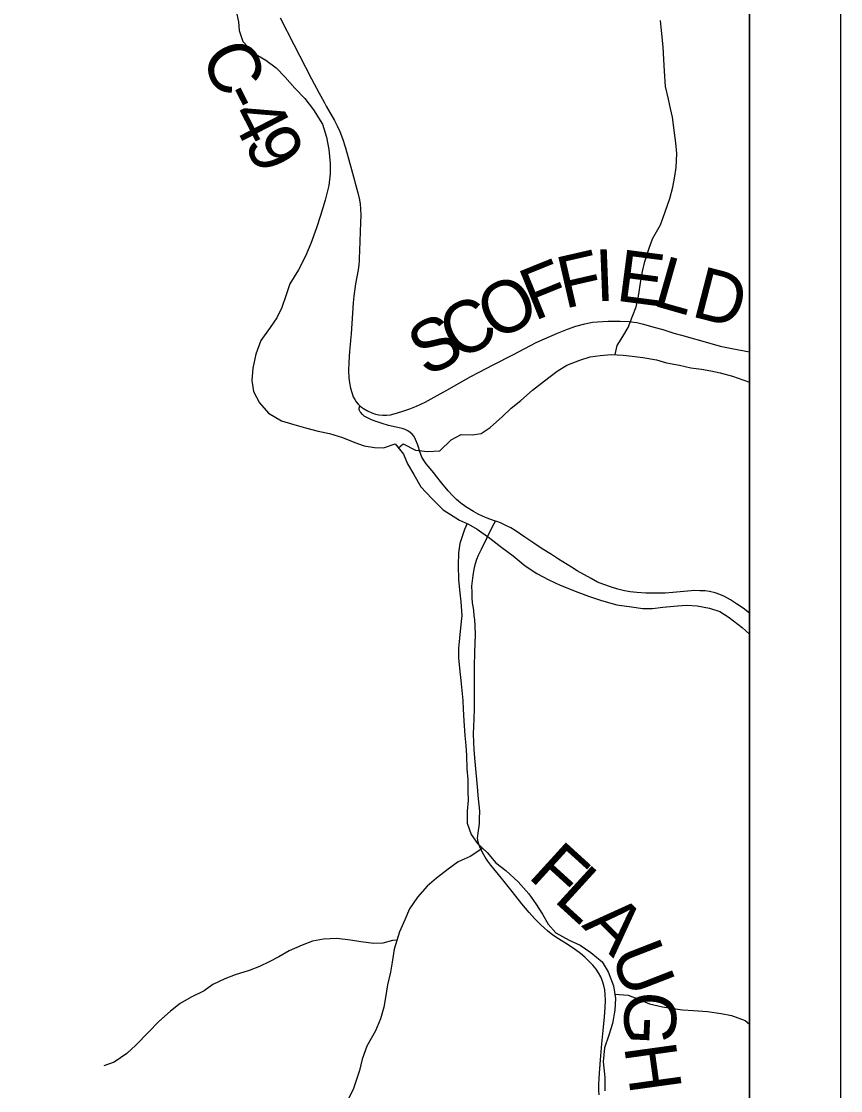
# Model space of a CAD drawing. Extents: x 0 to 34, y 0 to 22.
# Drawn here: x 8.316 to 9.214, y 14.754 to 15.927 of the extents above; entities that cross this region are included whole.
import ezdxf

# ---------------------------------------------------------------- set-up
doc = ezdxf.new("R2010")
doc.units = 0
for name, color, linetype in [('Default', 7, 'Continuous'), ('GM_X_County_Road', 7, 'Continuous'), ('GM_X_County_Road_Text', 7, 'Continuous'), ('GM_X_Minor_River', 7, 'Continuous'), ('GM_X_Township_Road', 7, 'Continuous'), ('GM_X_Township_Road_Text', 7, 'Continuous'), ('SH_Cut_Line', 7, 'Continuous'), ('SH_Data', 7, 'Continuous')]:
    doc.layers.add(name, color=color, linetype=linetype)

msp = doc.modelspace()

# ---------------------------------------------------------------- linework, layer by layer
at = {"layer": 'Default'}
msp.add_lwpolyline([(9.1142, 14.0996), (9.1142, 17.7402)], dxfattribs=at)
at = {"layer": 'GM_X_County_Road'}
for points in [[(8.5997, 15.9311), (8.6145, 15.9017), (8.634, 15.8643), (8.6424, 15.8483), (8.6477, 15.8385), (8.6502, 15.8342), (8.6592, 15.8186), (8.6623, 15.8125), (8.6652, 15.8062), (8.668, 15.7986), (8.6712, 15.7885), (8.6779, 15.7646), (8.6849, 15.7389), (8.6865, 15.7315), (8.6873, 15.7266), (8.6877, 15.7216), (8.6879, 15.7141), (8.6877, 15.7066), (8.6868, 15.6756), (8.6864, 15.6669), (8.6863, 15.6644), (8.6858, 15.6601), (8.685, 15.6545), (8.6823, 15.6392), (8.6805, 15.6257), (8.6798, 15.6184), (8.6773, 15.5843), (8.6767, 15.5769), (8.6763, 15.5726), (8.6755, 15.5652), (8.6749, 15.5528), (8.6747, 15.5442), (8.6751, 15.5361), (8.6757, 15.5307), (8.6768, 15.5246), (8.6781, 15.5199), (8.6798, 15.5153), (8.6814, 15.5121), (8.683, 15.5096), (8.685, 15.5073), (8.687, 15.5054)], [(8.687, 15.5054), (8.6889, 15.5038), (8.6911, 15.5024), (8.6953, 15.5), (8.7003, 15.4977), (8.7043, 15.4962), (8.7079, 15.4954), (8.7121, 15.495), (8.7163, 15.4951), (8.7205, 15.4956), (8.7247, 15.4965), (8.7329, 15.499), (8.7417, 15.502), (8.7491, 15.5051), (8.7586, 15.5095), (8.7717, 15.5166), (8.7858, 15.5244), (8.8078, 15.5372), (8.8177, 15.5424), (8.8332, 15.5502), (8.8556, 15.5618), (8.8804, 15.5747), (8.8894, 15.579), (8.9036, 15.5852), (8.9146, 15.5895), (8.924, 15.5927), (8.9336, 15.5954), (8.9372, 15.5962), (8.942, 15.5971), (8.9476, 15.5976), (8.9593, 15.5982), (8.9724, 15.5982), (8.9823, 15.5978), (8.9873, 15.5973), (8.9909, 15.5967), (8.9981, 15.5949), (9.0095, 15.5916), (9.0191, 15.589), (9.0315, 15.5851), (9.0399, 15.5828), (9.0709, 15.574), (9.0823, 15.5709), (9.095, 15.5681), (9.1084, 15.5656), (9.1142, 15.5645)], [(8.8356, 15.3789), (8.8285, 15.3814), (8.8216, 15.3841), (8.8166, 15.3865), (8.8117, 15.3892), (8.8033, 15.3945), (8.7978, 15.3986), (8.793, 15.4025), (8.7886, 15.4068), (8.7839, 15.4119), (8.777, 15.4206), (8.77, 15.4293), (8.768, 15.4317), (8.7596, 15.4417), (8.7575, 15.4448), (8.7551, 15.4491), (8.7534, 15.4531), (8.7501, 15.4631), (8.7481, 15.4684), (8.7464, 15.4716), (8.7445, 15.4741), (8.7422, 15.4762), (8.7396, 15.4779), (8.7367, 15.4792), (8.7334, 15.4804), (8.7268, 15.4819), (8.7184, 15.4838), (8.7113, 15.4858), (8.7048, 15.488), (8.6996, 15.4901), (8.6945, 15.4925), (8.6919, 15.4941), (8.69, 15.4957), (8.688, 15.4979), (8.6872, 15.4989), (8.6866, 15.5002), (8.6864, 15.5014), (8.6863, 15.5027), (8.6865, 15.504), (8.687, 15.5054)], [(9.1142, 15.2779), (9.1073, 15.2832), (9.1002, 15.2882), (9.0933, 15.2924), (9.0868, 15.296), (9.0817, 15.2983), (9.0765, 15.3003), (9.0705, 15.3015), (9.0656, 15.3022), (9.06, 15.3025), (9.0544, 15.3026), (9.0464, 15.3021), (9.0303, 15.3005), (9.0217, 15.2999), (9.0118, 15.2996), (9.0007, 15.2999), (8.9907, 15.3005), (8.9834, 15.3014), (8.9772, 15.3025), (8.97, 15.3042), (8.9617, 15.3066), (8.9546, 15.3091), (8.9477, 15.312), (8.9406, 15.3157), (8.9255, 15.3244), (8.9192, 15.3283), (8.905, 15.3372), (8.8971, 15.3421), (8.8871, 15.3484), (8.8778, 15.3546), (8.868, 15.3611), (8.8572, 15.3684), (8.8524, 15.3713), (8.8464, 15.3744), (8.8413, 15.3768), (8.8373, 15.3783), (8.8356, 15.3789)]]:
    msp.add_lwpolyline(points, dxfattribs=at)
at = {"layer": 'GM_X_Minor_River'}
for points in [[(8.5511, 15.9403), (8.5539, 15.9266), (8.5545, 15.9171), (8.5585, 15.9052), (8.5709, 15.8925), (8.584, 15.8847), (8.5953, 15.8762), (8.6046, 15.8662), (8.6158, 15.8539), (8.6266, 15.8427), (8.6363, 15.83), (8.646, 15.8143), (8.6503, 15.8002), (8.6531, 15.7865), (8.6544, 15.7713), (8.6543, 15.7599), (8.6529, 15.747), (8.6489, 15.7311), (8.6437, 15.7141), (8.6394, 15.7005), (8.6331, 15.6835), (8.6275, 15.6695), (8.6197, 15.6544), (8.6104, 15.6393), (8.6061, 15.6272), (8.6013, 15.6133), (8.5958, 15.6019), (8.5885, 15.5914), (8.5784, 15.5771), (8.5729, 15.562), (8.5696, 15.5465), (8.5687, 15.5332), (8.5704, 15.521), (8.577, 15.5088), (8.5867, 15.4972), (8.601, 15.4887), (8.6146, 15.4847), (8.6275, 15.4811), (8.6414, 15.4774), (8.6539, 15.475), (8.6679, 15.4706), (8.6814, 15.4651), (8.6916, 15.4615), (8.703, 15.4595), (8.7128, 15.4593), (8.7258, 15.4637), (8.7347, 15.4522), (8.7391, 15.4418), (8.7462, 15.43), (8.7539, 15.4166), (8.7659, 15.4035), (8.7782, 15.3911), (8.7962, 15.3799), (8.806, 15.3755), (8.8158, 15.3701), (8.8297, 15.36), (8.8428, 15.3499), (8.8552, 15.3406), (8.8683, 15.3298), (8.8811, 15.3213), (8.8942, 15.3143), (8.9067, 15.3084), (8.9259, 15.3009)], [(8.9671, 15.5615), (8.9693, 15.5715), (8.9755, 15.5813), (8.9813, 15.5914), (8.9861, 15.6039), (8.99, 15.6141), (8.9924, 15.6255), (8.9953, 15.6425), (8.997, 15.6528), (8.9994, 15.6637), (9.0038, 15.6773), (9.0081, 15.6887), (9.0167, 15.7038), (9.0214, 15.717), (9.027, 15.7329), (9.0302, 15.7453), (9.0322, 15.7552), (9.0339, 15.7669), (9.0345, 15.7821), (9.0336, 15.7939), (9.0322, 15.805), (9.0298, 15.8221), (9.0277, 15.8316), (9.0255, 15.8419), (9.0223, 15.8556), (9.021, 15.8724), (9.0205, 15.8853), (9.0195, 15.8993), (9.0179, 15.9172), (9.0166, 15.9283)], [(8.7293, 15.4592), (8.7345, 15.4636), (8.7481, 15.4565), (8.7613, 15.4552), (8.7746, 15.4561), (8.7873, 15.4681), (8.798, 15.4737), (8.8101, 15.4735), (8.82, 15.4749), (8.8299, 15.4816), (8.8434, 15.4935), (8.853, 15.5029), (8.8634, 15.5111), (8.8764, 15.5227), (8.8895, 15.5327), (8.9033, 15.5432), (8.914, 15.5499), (8.9281, 15.5554), (8.9395, 15.559), (8.9505, 15.5604), (8.9627, 15.5617), (8.9756, 15.5611), (8.9858, 15.5598), (8.9975, 15.5582), (9.0123, 15.5557), (9.0232, 15.5525), (9.0376, 15.55), (9.0501, 15.5471), (9.0618, 15.5455), (9.072, 15.5438), (9.0822, 15.5417), (9.0958, 15.5377), (9.1142, 15.5313)], [(8.8047, 15.3761), (8.8018, 15.3695), (8.7966, 15.3544), (8.7953, 15.3442), (8.7947, 15.3301), (8.7953, 15.3149), (8.7963, 15.3035), (8.7976, 15.2902), (8.7989, 15.2754), (8.7975, 15.2617), (8.7962, 15.2503), (8.7953, 15.2393), (8.7952, 15.2287), (8.7965, 15.2139), (8.7978, 15.204), (8.7988, 15.1929), (8.7998, 15.1819), (8.8004, 15.1724), (8.801, 15.1595), (8.8023, 15.1435), (8.8032, 15.1325), (8.8038, 15.1218), (8.8044, 15.107), (8.8054, 15.0952), (8.8055, 15.0827), (8.8058, 15.0724), (8.8048, 15.0607), (8.8047, 15.0474), (8.809, 15.0348), (8.8161, 15.0252), (8.8266, 15.0151), (8.8363, 15.004), (8.8471, 14.9955), (8.8606, 14.9831), (8.8722, 14.9697), (8.88, 14.9589), (8.8874, 14.9474), (8.8937, 14.9367), (8.9019, 14.9271), (8.9165, 14.9189), (8.9286, 14.9134), (8.9402, 14.9056), (8.9526, 14.8952), (8.9592, 14.8841), (8.9651, 14.8688), (8.9672, 14.8551), (8.9666, 14.8422), (8.9641, 14.8274), (8.9601, 14.8149), (8.9554, 14.801), (8.954, 14.7854), (8.9557, 14.7683), (8.9558, 14.7535)], [(8.9259, 15.3009), (8.9376, 15.2965), (8.9519, 15.2918), (8.9689, 15.287), (8.9848, 15.2848), (8.9973, 15.2831), (9.0079, 15.283), (9.0193, 15.2843), (9.0353, 15.286), (9.0455, 15.2866), (9.0569, 15.2857), (9.0705, 15.2832), (9.0818, 15.2796), (9.092, 15.273), (9.1062, 15.2622), (9.1142, 15.2547)], [(8.8217, 15.0198), (8.8079, 15.0109), (8.7949, 15.005), (8.7838, 14.9968), (8.7712, 14.9871), (8.7608, 14.9781), (8.7504, 14.9661), (8.7415, 14.9533), (8.7364, 14.9412), (8.7305, 14.928), (8.7245, 14.9091), (8.7224, 14.8947), (8.7207, 14.8837), (8.7175, 14.8701), (8.715, 14.8561), (8.7134, 14.8455), (8.7097, 14.8326), (8.7042, 14.8194), (8.6945, 14.8028), (8.6894, 14.7885), (8.6865, 14.776), (8.683, 14.765), (8.6798, 14.7552), (8.6732, 14.7424)], [(8.7277, 14.9191), (8.7228, 14.9187), (8.7121, 14.9158), (8.7022, 14.9155), (8.6879, 14.9173), (8.6769, 14.9189), (8.6617, 14.9207), (8.6473, 14.9201), (8.6352, 14.918), (8.6237, 14.9136), (8.6096, 14.9074), (8.5981, 14.9007), (8.5874, 14.8952), (8.5771, 14.89), (8.5657, 14.8856), (8.5504, 14.8809), (8.539, 14.8765), (8.5256, 14.8702), (8.5161, 14.8635), (8.5019, 14.8565), (8.4901, 14.8495), (8.4793, 14.8409), (8.4666, 14.8297), (8.4551, 14.8181), (8.4412, 14.8038), (8.4316, 14.7945), (8.4175, 14.7852), (8.4064, 14.7812)], [(8.9665, 14.8596), (8.9813, 14.8587), (8.9937, 14.854), (9.0046, 14.8492), (9.019, 14.846), (9.0307, 14.8439), (9.0409, 14.8426), (9.053, 14.8417), (9.0682, 14.8407), (9.0833, 14.8386), (9.0947, 14.8362), (9.1094, 14.831), (9.1142, 14.8269)]]:
    msp.add_lwpolyline(points, dxfattribs=at)
at = {"layer": 'GM_X_Township_Road'}
for points in [[(8.8173, 15.0395), (8.8175, 15.0415), (8.8181, 15.047), (8.8183, 15.0521), (8.8184, 15.0605), (8.8169, 15.0779), (8.8163, 15.0834), (8.8135, 15.115), (8.8123, 15.128), (8.8119, 15.136), (8.8118, 15.1453), (8.8123, 15.1616), (8.8126, 15.1733), (8.8129, 15.197), (8.8129, 15.2186), (8.813, 15.2353), (8.8138, 15.2539), (8.8135, 15.2638), (8.813, 15.2707), (8.8125, 15.2749), (8.8121, 15.2811), (8.8107, 15.289), (8.8101, 15.2948), (8.8101, 15.3007), (8.8099, 15.3075), (8.8104, 15.3132), (8.8112, 15.3193), (8.8124, 15.326), (8.8139, 15.3324), (8.8152, 15.3369), (8.8171, 15.3415), (8.8205, 15.3482), (8.8327, 15.3735), (8.8356, 15.3789)], [(8.9496, 14.7494), (8.9492, 14.7543), (8.9491, 14.7599), (8.9494, 14.768), (8.951, 14.7878), (8.9524, 14.8051), (8.9539, 14.8199), (8.9554, 14.8347), (8.9562, 14.8446), (8.9565, 14.8533), (8.9562, 14.8589), (8.9556, 14.8645), (8.9546, 14.8693), (8.9532, 14.8741), (8.9512, 14.8787), (8.9488, 14.883), (8.946, 14.8871), (8.9424, 14.8914), (8.9382, 14.896), (8.9337, 14.9002), (8.929, 14.9042), (8.9236, 14.9083), (8.9153, 14.9137), (8.9048, 14.9203), (8.8987, 14.9246), (8.8929, 14.9293), (8.8855, 14.9359), (8.8788, 14.9424), (8.8725, 14.9493), (8.8646, 14.9588), (8.8539, 14.9724), (8.8422, 14.9869), (8.8305, 15.0012), (8.8272, 15.0057), (8.8245, 15.0099), (8.8215, 15.0153), (8.8186, 15.0215), (8.8171, 15.0256), (8.8163, 15.0286), (8.8162, 15.0311), (8.8164, 15.0335), (8.8173, 15.0395)]]:
    msp.add_lwpolyline(points, dxfattribs=at)
at = {"layer": 'SH_Cut_Line'}
msp.add_lwpolyline([(9.1142, 14.0996), (9.1142, 20.8996), (2.3142, 20.8996)], dxfattribs=at)
at = {"layer": 'SH_Data'}
for p, q in [((9.2142, 20.9996), (9.2142, 13.9996)), ((9.1142, 20.8996), (9.1142, 14.0996))]:
    msp.add_line(p, q, dxfattribs=at)

# ---------------------------------------------------------------- texts
at = {"layer": 'GM_X_County_Road_Text'}
for s, rotation, p in [('C', 295.2925, (8.5115, 15.8899)), ('-', 296.8652, (8.5322, 15.8462)), ('4', 297.3066, (8.543, 15.825)), ('9', 297.4382, (8.5591, 15.7938)), ('F', 12.893, (8.9113, 15.6117)), ('I', 2.2173, (8.9459, 15.6199)), ('E', 352.6145, (8.9667, 15.6209)), ('F', 22.0288, (8.8781, 15.5981)), ('L', 344.0988, (9.0067, 15.6159)), ('D', 345.5617, (9.0491, 15.6039)), ('O', 27.1214, (8.8348, 15.5758)), ('C', 27.8306, (8.7937, 15.5541)), ('S', 27.8316, (8.7598, 15.5362))]:
    msp.add_text(s, height=0.0568, rotation=rotation, dxfattribs=at).set_placement(p)
at = {"layer": 'GM_X_Township_Road_Text'}
for s, rotation, p in [('F', 317.6988, (8.8701, 14.9884)), ('L', 317.648, (8.8984, 14.9626)), ('A', 315.0219, (8.9293, 14.9344)), ('U', 291.2474, (8.9613, 14.9043)), ('G', 267.3799, (8.9784, 14.8638)), ('H', 277.9074, (8.9767, 14.8025))]:
    msp.add_text(s, height=0.0568, rotation=rotation, dxfattribs=at).set_placement(p)

doc.saveas('drawing.dxf')
